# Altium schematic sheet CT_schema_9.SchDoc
size 274 x 160 mm
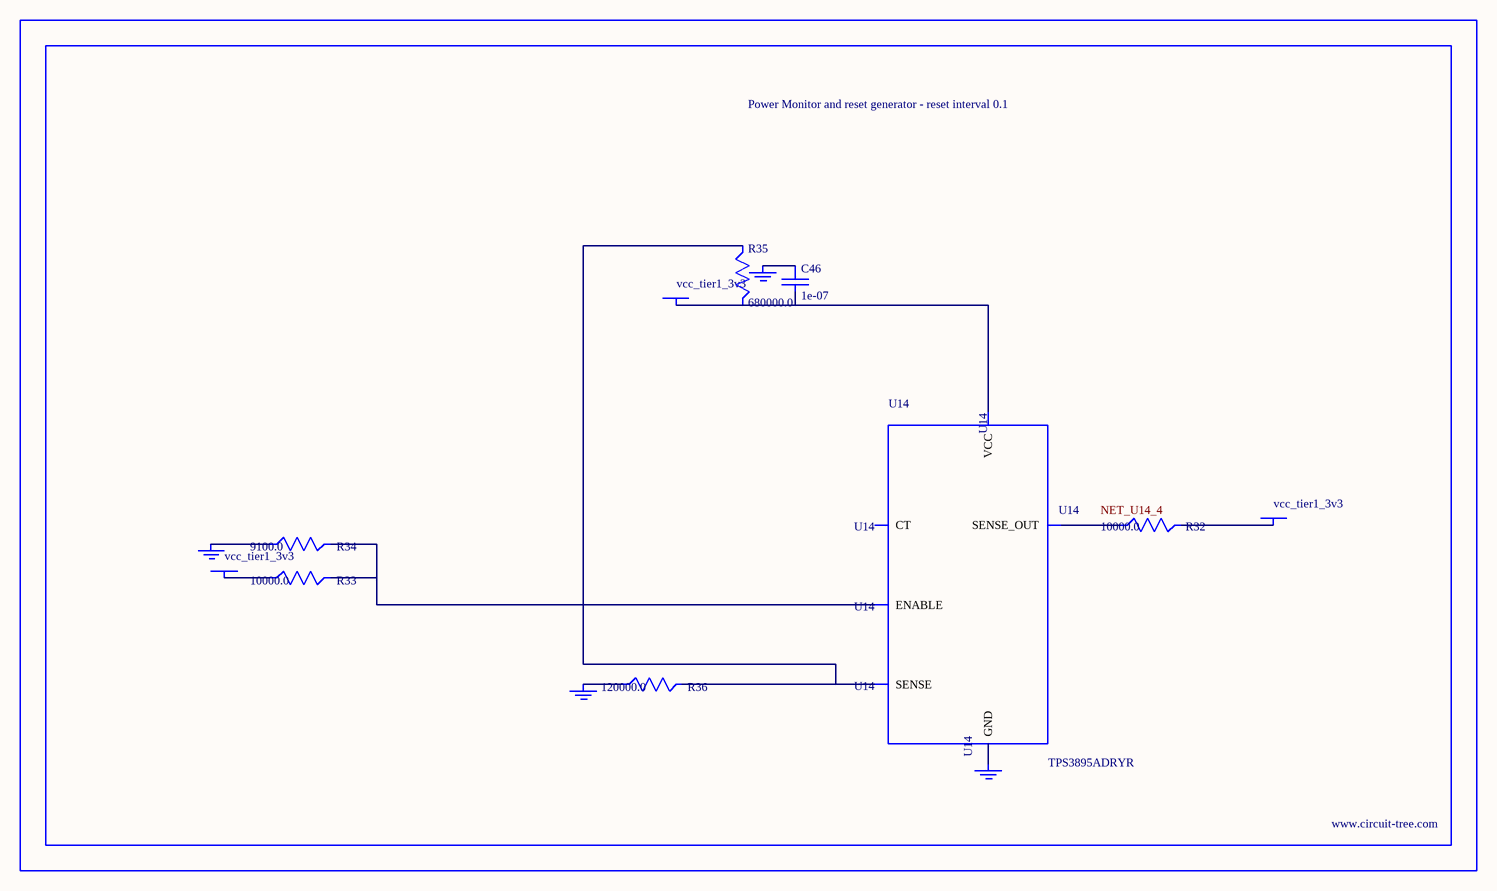
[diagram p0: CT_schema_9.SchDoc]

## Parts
BORDER8  (no value)
C46  1e-07  [C0402]
GND_INSTANCE_8_0  (no value)
GND_INSTANCE_8_1  (no value)
GND_INSTANCE_8_2  (no value)
GND_INSTANCE_8_3  (no value)
POWER_INSTANCE_8_0  vcc_tier1_3v3
POWER_INSTANCE_8_1  vcc_tier1_3v3
POWER_INSTANCE_8_2  vcc_tier1_3v3
R32  10000.0  [R0603]
R33  10000.0  [R0603]
R34  9100.0  [R0603]
R35  680000.0  [R0603]
R36  120000.0  [R0603]
U14  TPS3895ADRYR  [SON-6]

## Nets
NetC46_1: C46.1 GND_INSTANCE_8_2.0(GND)
NetC46_2: C46.2 POWER_INSTANCE_8_2.0(PWR) R35.2 U14.6(VCC)
NetGND_INSTANCE_8_0_0: GND_INSTANCE_8_0.0(GND) R34.1
NetGND_INSTANCE_8_1_0: GND_INSTANCE_8_1.0(GND) R36.1
NetGND_INSTANCE_8_3_0: GND_INSTANCE_8_3.0(GND) U14.2(GND)
NetPOWER_INSTANCE_8_0_0: POWER_INSTANCE_8_0.0(PWR) R33.1
NetPOWER_INSTANCE_8_1_0: POWER_INSTANCE_8_1.0(PWR) R32.2
NetR32_1: R32.1 U14.4(SENSE_OUT)
NetR33_2: R33.2 R34.2 U14.1(ENABLE)
NetR35_1: R35.1 R36.2 U14.3(SENSE)

Not connected (* = marked no-connect by the designer): U14 5(CT)

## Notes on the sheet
- Labels drawn without touching a wire or pin: NET_U14_4

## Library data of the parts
BORDER8 = BORDER_PAGE8
C46 = C0402C104K3RACTU
GND_INSTANCE_8_0-GND_INSTANCE_8_3 = GND
POWER_INSTANCE_8_0-POWER_INSTANCE_8_2 = PWR
R32 R33 = RC0603JR-0710KL
R34 = RC0603JR-079K1L
R35 = RC0603JR-07680KL
R36 = RC0603JR-07120KL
